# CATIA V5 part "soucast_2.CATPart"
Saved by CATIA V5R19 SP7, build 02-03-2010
Part number: Part2
Material "Steel": density 7860 kg/m3, Young's modulus 2e+11 Pa, Poisson ratio 0.266, thermal expansion 1.17e-05 1/K
Bounding box of the stored display mesh (mm): x -70 to 70, y -70 to 70, z 0 to 80
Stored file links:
  D:\CATIA\TECHNODAT\FEM_TESTOVANI\SROUBOVY_SPOJ\soucast_2.CATPart
  Part1.CATPart
  C:\Program Files\Dassault Systemes\B19\win_b64\reffiles\standard\MetricThickPitch.txt
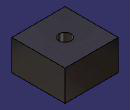
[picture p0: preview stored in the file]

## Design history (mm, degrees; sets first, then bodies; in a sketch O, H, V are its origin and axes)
Body1 (main body), material "Steel"
  Sketch1 on xy-plane, origin (0, 0, 0), H (1, 0, 0), V (0, 1, 0)
    line L1 (70, 70) -> (70, -70)
    line L2 (70, -70) -> (-70, -70)
    line L3 (-70, -70) -> (-70, 70)
    line L4 (-70, 70) -> (70, 70)
    vertical: L1 V, L3 V
    horizontal: L2 H, L4 H
    equidistance: L1 L3 O, L2 L4 O
  Pad1: profile Sketch1, direction (0, 0, 1), length 80
  Sketch2 on end face of Pad1, origin (0, 0, 80), H (1, 0, 0), V (0, 1, 0)
    point P1 (0, 0)
  Hole1: placed by Sketch2, at (0, 0, 80) direction (0, 0, -1), diameter 32, through (limit type 6)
